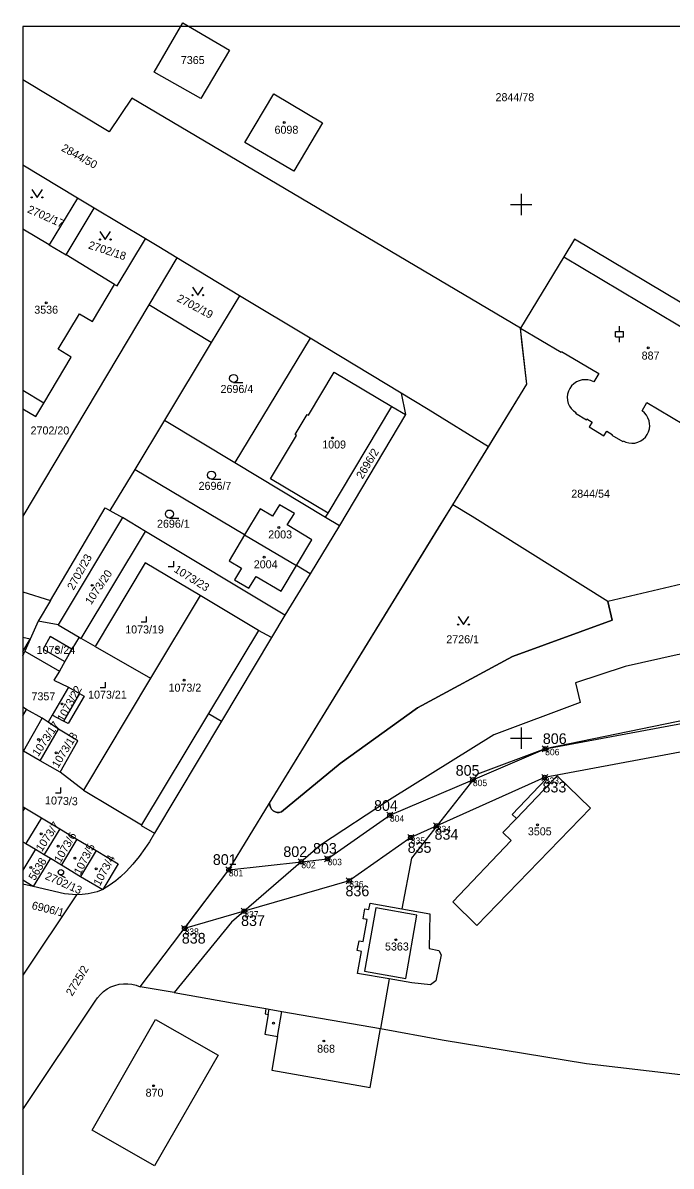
# Model space of a CAD drawing. Extents: x -800194 to -799078, y -1007177 to -1006597.
# Drawn here: x -800193.4 to -800071.9, y -1006980.2 to -1006766 of the extents above; entities that cross this region are included whole.
import ezdxf

# ---------------------------------------------------------------- set-up
doc = ezdxf.new("R2010")
doc.units = 0
for name, color, linetype in [('Dočasné zábory', 7, 'Continuous'), ('Legenda 1', 7, 'Continuous'), ('Ramove udaje', 7, 'Continuous'), ('Vrstva 53', 7, 'Continuous'), ('Vrstva 55', 7, 'Continuous'), ('Vrstva 56', 7, 'Continuous'), ('Vrstva 57', 7, 'Continuous'), ('Vrstva 58', 7, 'Continuous'), ('Vrstva 59', 7, 'Continuous'), ('Vrstva 60', 7, 'Continuous')]:
    doc.layers.add(name, color=color, linetype=linetype)

msp = doc.modelspace()

# ---------------------------------------------------------------- linework, layer by layer
at = {"layer": 'Dočasné zábory'}
for p, q in [((-800096.06, -1006902.6), (-800094.92, -1006901.46)), ((-800096.06, -1006901.46), (-800094.92, -1006902.6)), ((-800109.6, -1006908.39), (-800108.47, -1006907.25)), ((-800109.6, -1006907.25), (-800108.47, -1006908.39)), ((-800096.14, -1006907.95), (-800095.01, -1006906.82)), ((-800096.14, -1006906.82), (-800095.01, -1006907.95)), ((-800125.15, -1006915.04), (-800124.02, -1006913.9)), ((-800125.15, -1006913.9), (-800124.02, -1006915.04)), ((-800116.39, -1006917.03), (-800115.25, -1006915.9)), ((-800116.39, -1006915.9), (-800115.25, -1006917.03)), ((-800121.25, -1006919.21), (-800120.11, -1006918.08)), ((-800121.25, -1006918.08), (-800120.11, -1006919.21)), ((-800141.76, -1006923.76), (-800140.62, -1006922.63)), ((-800141.76, -1006922.63), (-800140.62, -1006923.76)), ((-800136.83, -1006923.21), (-800135.7, -1006922.08)), ((-800136.83, -1006922.08), (-800135.7, -1006923.21)), ((-800155.35, -1006925.3), (-800154.21, -1006924.16)), ((-800155.35, -1006924.16), (-800154.21, -1006925.3)), ((-800132.78, -1006927.34), (-800131.64, -1006926.21)), ((-800132.78, -1006926.21), (-800131.64, -1006927.34)), ((-800152.46, -1006933.02), (-800151.33, -1006931.88)), ((-800152.46, -1006931.88), (-800151.33, -1006933.02)), ((-800163.65, -1006936.24), (-800162.52, -1006935.11)), ((-800163.65, -1006935.11), (-800162.52, -1006936.24))]:
    msp.add_line(p, q, dxfattribs=at)
msp.add_lwpolyline([(-799934.68, -1006921.09), (-799969.58, -1006905.87), (-799994.89, -1006899.12), (-800033.61, -1006895.83), (-800040.39, -1006897.1), (-800095.58, -1006907.39), (-800115.82, -1006916.46), (-800120.68, -1006918.64), (-800132.21, -1006926.78), (-800151.89, -1006932.45), (-800163.09, -1006935.68), (-800154.78, -1006924.73), (-800141.19, -1006923.2), (-800136.27, -1006922.64), (-800124.59, -1006914.47), (-800109.03, -1006907.82), (-800095.49, -1006902.03), (-800049.12, -1006893.41), (-800047.13, -1006893.07), (-800033.82, -1006890.8), (-799994.03, -1006894.18), (-799967.93, -1006901.13), (-799932.44, -1006916.61)], dxfattribs=at)
for centre in [(-800095.49, -1006902.03), (-800109.03, -1006907.82), (-800095.58, -1006907.39), (-800124.59, -1006914.47), (-800115.82, -1006916.46), (-800120.68, -1006918.64), (-800141.19, -1006923.2), (-800136.27, -1006922.64), (-800154.78, -1006924.73), (-800132.21, -1006926.78), (-800151.89, -1006932.45), (-800163.09, -1006935.68)]:
    msp.add_circle(centre, 0.4, dxfattribs=at)
at = {"layer": 'Legenda 1'}
msp.add_lwpolyline([(-800193.4, -1007176.65), (-799312.4, -1007176.65), (-799312.4, -1006766.65), (-800193.4, -1006766.65)], close=True, dxfattribs=at)
at = {"layer": 'Ramove udaje'}
for p, q in [((-800100, -1006798), (-800100, -1006802)), ((-800102, -1006800), (-800100, -1006800)), ((-800100, -1006800), (-800098, -1006800)), ((-800100, -1006898), (-800100, -1006902)), ((-800102, -1006900), (-800100, -1006900)), ((-800100, -1006900), (-800098, -1006900))]:
    msp.add_line(p, q, dxfattribs=at)
at = {"layer": 'Vrstva 53'}
msp.add_lwpolyline([(-800067.83, -1006870.66), (-800083.75, -1006874.38), (-800082.93, -1006877.89), (-800101.58, -1006884.73), (-800119.41, -1006894.35), (-800133.89, -1006904.78), (-800144.92, -1006913.85), (-800145.32, -1006913.94), (-800145.72, -1006913.94), (-800146.12, -1006913.83), (-800146.47, -1006913.63), (-800146.77, -1006913.35), (-800147, -1006912.99), (-800147.12, -1006912.61), (-800147.15, -1006912.2), (-800112.81, -1006856.29), (-800098.93, -1006833.67), (-800100.11, -1006823.15), (-800172.96, -1006780.08), (-800177.22, -1006786.39), (-800193.4, -1006776.62)], dxfattribs=at)
at = {"layer": 'Vrstva 55'}
for p, q in [((-800183.18, -1006798.79), (-800193.4, -1006792.65)), ((-800180.01, -1006800.69), (-800183.18, -1006798.79)), ((-800170.41, -1006806.46), (-800180.01, -1006800.69)), ((-800164.51, -1006810.02), (-800169.77, -1006818.83)), ((-800152.8, -1006817.1), (-800164.51, -1006810.02)), ((-800152.8, -1006817.1), (-800158.09, -1006825.87)), ((-800139.57, -1006825.06), (-800152.8, -1006817.1)), ((-800158.09, -1006825.87), (-800169.77, -1006818.83)), ((-800158.09, -1006825.87), (-800166.86, -1006840.41)), ((-800139.57, -1006825.06), (-800153.65, -1006848.37)), ((-800122.47, -1006835.35), (-800139.57, -1006825.06)), ((-800122.47, -1006835.35), (-800121.67, -1006839.36)), ((-800166.86, -1006840.41), (-800172.41, -1006849.68)), ((-800166.86, -1006840.41), (-800153.65, -1006848.37)), ((-800121.67, -1006839.36), (-800134.05, -1006860.17)), ((-800112.81, -1006856.29), (-800106.13, -1006845.4)), ((-800172.41, -1006849.68), (-800177.12, -1006857.35)), ((-800153.65, -1006848.37), (-800136.64, -1006858.61)), ((-800177.12, -1006857.35), (-800174.74, -1006858.64)), ((-800136.64, -1006858.61), (-800134.05, -1006860.17)), ((-800174.74, -1006858.64), (-800186.75, -1006878.76)), ((-800170.43, -1006861.26), (-800174.74, -1006858.64)), ((-800134.05, -1006860.17), (-800139.55, -1006869.21)), ((-800182.47, -1006881.33), (-800170.43, -1006861.26)), ((-800144.27, -1006876.97), (-800170.43, -1006861.26)), ((-800151.83, -1006861.89), (-800142.1, -1006867.68)), ((-800139.55, -1006869.21), (-800144.27, -1006876.97)), ((-800139.55, -1006869.21), (-800142.1, -1006867.68)), ((-800067.83, -1006870.66), (-800083.75, -1006874.38)), ((-800193.4, -1006872.57), (-800188.22, -1006874.2)), ((-800160.18, -1006873.27), (-800169.49, -1006888.81)), ((-800188.22, -1006874.2), (-800190.53, -1006878.1)), ((-800144.27, -1006876.97), (-800146.81, -1006881.14)), ((-800190.53, -1006878.1), (-800192.02, -1006881.48)), ((-800186.75, -1006878.76), (-800190.53, -1006878.1)), ((-800186.75, -1006878.76), (-800182.83, -1006881.12)), ((-800192.02, -1006881.48), (-800193.4, -1006881.15)), ((-800192.02, -1006881.48), (-800193.01, -1006883.73)), ((-800182.83, -1006881.12), (-800182.47, -1006881.33)), ((-800179.85, -1006882.84), (-800182.47, -1006881.33)), ((-800193.4, -1006884.61), (-800193.01, -1006883.73)), ((-800193.01, -1006883.73), (-800186.55, -1006887.44)), ((-800179.85, -1006882.84), (-800169.49, -1006888.81)), ((-800186.55, -1006887.44), (-800187.59, -1006889.15)), ((-800184.82, -1006890.46), (-800187.9, -1006895.7)), ((-800187.59, -1006889.15), (-800184.82, -1006890.46)), ((-800169.49, -1006888.81), (-800182.05, -1006909.75)), ((-800192.7, -1006894.63), (-800193.4, -1006894.24)), ((-800193.4, -1006895.86), (-800192.7, -1006894.63)), ((-800189.78, -1006896.28), (-800192.7, -1006894.63)), ((-800193.28, -1006902.47), (-800189.78, -1006896.28)), ((-800188.68, -1006897.03), (-800189.78, -1006896.28)), ((-800187.9, -1006895.7), (-800188.68, -1006897.03)), ((-800186.7, -1006898.36), (-800188.68, -1006897.03)), ((-800190.15, -1006904.25), (-800186.7, -1006898.36)), ((-800183.1, -1006900.51), (-800186.7, -1006898.36)), ((-800186.38, -1006906.38), (-800183.1, -1006900.51)), ((-800193.28, -1006902.47), (-800193.4, -1006902.4)), ((-800190.15, -1006904.25), (-800193.28, -1006902.47)), ((-800186.38, -1006906.38), (-800190.15, -1006904.25)), ((-800182.05, -1006909.75), (-800186.38, -1006906.38)), ((-800193.05, -1006913.06), (-800193.4, -1006913.64)), ((-800193.05, -1006913.06), (-800189.92, -1006914.94)), ((-800189.92, -1006914.94), (-800192.83, -1006919.78)), ((-800189.92, -1006914.94), (-800186.48, -1006917.01)), ((-800186.48, -1006917.01), (-800189.39, -1006921.85)), ((-800186.48, -1006917.01), (-800183.26, -1006918.94)), ((-800193.4, -1006919.44), (-800192.83, -1006919.78)), ((-800192.83, -1006919.78), (-800191.06, -1006920.85)), ((-800183.26, -1006918.94), (-800186.17, -1006923.78)), ((-800183.26, -1006918.94), (-800179.67, -1006921.09)), ((-800191.06, -1006920.85), (-800193.4, -1006924.74)), ((-800188.23, -1006922.55), (-800191.44, -1006927.83)), ((-800191.06, -1006920.85), (-800189.39, -1006921.85)), ((-800189.39, -1006921.85), (-800188.23, -1006922.55)), ((-800188.23, -1006922.55), (-800186.17, -1006923.78)), ((-800179.67, -1006921.09), (-800182.6, -1006925.93)), ((-800120.56, -1006922.5), (-800122.37, -1006932)), ((-800186.17, -1006923.78), (-800182.6, -1006925.93)), ((-800191.44, -1006927.83), (-800193.4, -1006926.67)), ((-800182.6, -1006925.93), (-800178.43, -1006928.42)), ((-800191.44, -1006927.83), (-800193.4, -1006927.37)), ((-800183.37, -1006929.41), (-800193.4, -1006944.43)), ((-800124.76, -1006945.16), (-800126.38, -1006954.46)), ((-800165.04, -1006947.7), (-800171.39, -1006946.62))]:
    msp.add_line(p, q, dxfattribs=at)
for points in [[(-800163.38, -1006765.95), (-800154.63, -1006771.06), (-800160.01, -1006780.11), (-800168.77, -1006775.17), (-800163.38, -1006765.95)], [(-800100.11, -1006823.15), (-800172.96, -1006780.08), (-800177.22, -1006786.39), (-800193.4, -1006776.62)], [(-800146.37, -1006779.25), (-800137.24, -1006784.69), (-800142.62, -1006793.72), (-800151.76, -1006788.38), (-800146.37, -1006779.25)], [(-800183.18, -1006798.79), (-800188.44, -1006807.58), (-800193.4, -1006804.6)], [(-800176.19, -1006814.96), (-800185.31, -1006809.46), (-800180.01, -1006800.69)], [(-800176.19, -1006814.96), (-800175.72, -1006815.24), (-800170.41, -1006806.46)], [(-800164.51, -1006810.02), (-800167.92, -1006807.96), (-800170.41, -1006806.46)], [(-800020.66, -1006847.86), (-800026.06, -1006844.58), (-800089.97, -1006806.47), (-800092.01, -1006809.83), (-800100.11, -1006823.15)], [(-800193.4, -1006838.29), (-800190.96, -1006839.75), (-800189.46, -1006837.23), (-800184.32, -1006828.6), (-800186.75, -1006827.14), (-800182.78, -1006820.48), (-800180.34, -1006821.93), (-800176.19, -1006814.96)], [(-800169.77, -1006818.83), (-800193.4, -1006858.41)], [(-800106.13, -1006845.4), (-800098.93, -1006833.67), (-800099.83, -1006825.69), (-800100.11, -1006823.15)], [(-800100.11, -1006823.15), (-800092.48, -1006827.68), (-800092.4, -1006827.53), (-800085.43, -1006831.67), (-800086.36, -1006833.24)], [(-800086.36, -1006833.24), (-800086.9, -1006833.01), (-800087.46, -1006832.87), (-800088.05, -1006832.83), (-800088.53, -1006832.88), (-800089.09, -1006833.02), (-800089.63, -1006833.26), (-800090.11, -1006833.59), (-800090.53, -1006833.99), (-800090.88, -1006834.46), (-800091.13, -1006834.97), (-800091.29, -1006835.52), (-800091.35, -1006836.09), (-800091.31, -1006836.66), (-800091.3, -1006836.72), (-800091.15, -1006837.27), (-800090.91, -1006837.79), (-800090.58, -1006838.25), (-800090.17, -1006838.66), (-800089.7, -1006838.98)], [(-800106.13, -1006845.4), (-800117.43, -1006838.45), (-800120.08, -1006836.82), (-800122.47, -1006835.35)], [(-800077.33, -1006838.69), (-800076.4, -1006837.12), (-800069.48, -1006841.22), (-800069.56, -1006841.35), (-800061.89, -1006845.9), (-800061.61, -1006845.43), (-800053.39, -1006850.31), (-800053.68, -1006850.78), (-800042.78, -1006857.25)], [(-800136.64, -1006858.61), (-800136.18, -1006857.85), (-800124.24, -1006837.87), (-800121.67, -1006839.36)], [(-800089.7, -1006838.98), (-800089.78, -1006839.11), (-800087.76, -1006840.33), (-800087.69, -1006840.2), (-800086.68, -1006840.8), (-800087.24, -1006841.68), (-800084.46, -1006843.37), (-800083.93, -1006842.46), (-800082.91, -1006843.08), (-800082.98, -1006843.21), (-800080.94, -1006844.44), (-800080.86, -1006844.31)], [(-800080.86, -1006844.31), (-800080.34, -1006844.55), (-800079.78, -1006844.7), (-800079.21, -1006844.75), (-800078.65, -1006844.71), (-800078.09, -1006844.56), (-800077.57, -1006844.32), (-800077.09, -1006843.99), (-800076.68, -1006843.59), (-800076.35, -1006843.12), (-800076.1, -1006842.6), (-800075.95, -1006842.04), (-800075.89, -1006841.47), (-800075.91, -1006841.1), (-800076.01, -1006840.53), (-800076.22, -1006839.99), (-800076.51, -1006839.49), (-800076.89, -1006839.06), (-800077.33, -1006838.69)], [(-800151.83, -1006861.89), (-800172.32, -1006849.75), (-800172.41, -1006849.68)], [(-800142.1, -1006867.68), (-800139.22, -1006862.87), (-800143.86, -1006860.02), (-800142.5, -1006857.92), (-800145.28, -1006856.27), (-800146.57, -1006858.42), (-800148.9, -1006857.02), (-800151.83, -1006861.89)], [(-800147.15, -1006912.2), (-800114.97, -1006859.8), (-800112.81, -1006856.29)], [(-800083.75, -1006874.38), (-800109.15, -1006858.49), (-800112.81, -1006856.29)], [(-800188.22, -1006874.2), (-800177.98, -1006856.88), (-800177.12, -1006857.35)], [(-800151.83, -1006861.89), (-800154.75, -1006866.76), (-800152.43, -1006868.16), (-800153.72, -1006870.34), (-800151.03, -1006871.91), (-800149.68, -1006869.74), (-800144.98, -1006872.49), (-800142.1, -1006867.68)], [(-800160.18, -1006873.27), (-800170.48, -1006867.17), (-800179.85, -1006882.84)], [(-800146.81, -1006881.14), (-800149.24, -1006879.83), (-800160.18, -1006873.27)], [(-800144.92, -1006913.85), (-800133.89, -1006904.78), (-800119.41, -1006894.35), (-800101.58, -1006884.73), (-800082.93, -1006877.89), (-800083.75, -1006874.38)], [(-799964.79, -1006890.84), (-799979.01, -1006885.96), (-799998.45, -1006881.67), (-800018.08, -1006879.48), (-800038.51, -1006879.76), (-800056.43, -1006881.95), (-800070.76, -1006884.38), (-800080.47, -1006886.59), (-800089.79, -1006889.63), (-800088.91, -1006893.34), (-800105.12, -1006899.41), (-800124.67, -1006911.59), (-800137.62, -1006920.11), (-800154.3, -1006934.53), (-800165.04, -1006947.7)], [(-800193.4, -1006883.76), (-800192.02, -1006881.48)], [(-800182.83, -1006881.12), (-800184.21, -1006883.32), (-800185.51, -1006885.63), (-800186.55, -1006887.44)], [(-800146.81, -1006881.14), (-800156.19, -1006896.85), (-800168.72, -1006917.84)], [(-800184.82, -1006890.46), (-800182.76, -1006891.66), (-800181.9, -1006892.16), (-800184.93, -1006897.3), (-800185.8, -1006896.83), (-800187.9, -1006895.7)], [(-800048.34, -1006892.35), (-800095.49, -1006902.03), (-800108.2, -1006906.76), (-800120.56, -1006922.5)], [(-800094.49, -1006908.41), (-800093.24, -1006907.11), (-800087, -1006913.15), (-800108.28, -1006935.11), (-800112.78, -1006930.68), (-800101.83, -1006919.22), (-800103.39, -1006917.73), (-800100.86, -1006915.08), (-800101.66, -1006914.32), (-800095.28, -1006907.65), (-800094.49, -1006908.41)], [(-800182.05, -1006909.75), (-800171.15, -1006916.28), (-800171.22, -1006916.39), (-800168.72, -1006917.84)], [(-800171.39, -1006946.62), (-800154.78, -1006924.73), (-800147.15, -1006912.2)], [(-800147.15, -1006912.2), (-800147.12, -1006912.61), (-800147, -1006912.99), (-800146.78, -1006913.34), (-800146.77, -1006913.35), (-800146.47, -1006913.63), (-800146.12, -1006913.83), (-800145.72, -1006913.94), (-800145.32, -1006913.94), (-800144.92, -1006913.85)], [(-800193.4, -1006912.85), (-800193.05, -1006913.06)], [(-800168.72, -1006917.84), (-800169.66, -1006919.43), (-800170.52, -1006920.73), (-800171.62, -1006922.22), (-800172.79, -1006923.65), (-800174.04, -1006925.01), (-800175.11, -1006926.02), (-800176, -1006926.76), (-800177.19, -1006927.63), (-800178.43, -1006928.42)], [(-800179.67, -1006921.09), (-800175.54, -1006923.58), (-800178.43, -1006928.42)], [(-800183.37, -1006929.41), (-800185.59, -1006929.21), (-800191.44, -1006927.83)], [(-800178.43, -1006928.42), (-800179.48, -1006928.81), (-800180.04, -1006928.97), (-800181.14, -1006929.22), (-800182.25, -1006929.36), (-800183.37, -1006929.41)], [(-800124.76, -1006945.16), (-800130.67, -1006944.14), (-800129.93, -1006939.99), (-800130.7, -1006939.85), (-800130.36, -1006937.99), (-800129.59, -1006938.12), (-800128.86, -1006934.02), (-800129.62, -1006933.9), (-800129.29, -1006932.03), (-800128.52, -1006932.16), (-800128.31, -1006930.95), (-800122.37, -1006932)], [(-800122.37, -1006932), (-800117.1, -1006932.94), (-800117.23, -1006939.43), (-800115.39, -1006939.82), (-800114.95, -1006940.64), (-800115.98, -1006945.49), (-800117, -1006946.26), (-800120.48, -1006945.9), (-800124.76, -1006945.16)], [(-800179.84, -1006949.35), (-800179.39, -1006948.67), (-800178.86, -1006948.05), (-800178.26, -1006947.5), (-800177.6, -1006947.03), (-800176.89, -1006946.65), (-800176.16, -1006946.36), (-800175.37, -1006946.16), (-800174.56, -1006946.05), (-800173.75, -1006946.05), (-800172.94, -1006946.14), (-800172.15, -1006946.33), (-800171.39, -1006946.62)], [(-800165.04, -1006947.7), (-800154.15, -1006949.62), (-800147.83, -1006950.72)], [(-800193.4, -1006969.65), (-800179.84, -1006949.35)], [(-800147.83, -1006950.72), (-800148, -1006951.71), (-800147.41, -1006951.81), (-800148.05, -1006955.52), (-800145.68, -1006955.92), (-800146.75, -1006962.28), (-800128.29, -1006965.5), (-800126.38, -1006954.46)], [(-800147.83, -1006950.72), (-800147.24, -1006950.83), (-800144.85, -1006951.24), (-800126.38, -1006954.46)], [(-800156.78, -1006959.44), (-800168.69, -1006980.17), (-800180.42, -1006973.53), (-800168.51, -1006952.75), (-800156.78, -1006959.44)], [(-800126.38, -1006954.46), (-800114.82, -1006956.57), (-800087.75, -1006960.99), (-799990.59, -1006972.38), (-799910.85, -1006981.15)]]:
    msp.add_lwpolyline(points, dxfattribs=at)
at = {"layer": 'Vrstva 56'}
for p, q in [((-800188.44, -1006807.58), (-800185.31, -1006809.46)), ((-800092.01, -1006809.83), (-800054.01, -1006832.46)), ((-800139.86, -1006839.49), (-800135.03, -1006831.4)), ((-800135.03, -1006831.4), (-800124.24, -1006837.87)), ((-800189.46, -1006837.23), (-800193.4, -1006834.87)), ((-800142.38, -1006843.12), (-800140.12, -1006839.33)), ((-800140.12, -1006839.33), (-800139.86, -1006839.49)), ((-800146.98, -1006851.4), (-800142.12, -1006843.27)), ((-800142.12, -1006843.27), (-800142.38, -1006843.12)), ((-800136.18, -1006857.85), (-800146.98, -1006851.4)), ((-800149.24, -1006879.83), (-800158.6, -1006895.39)), ((-800188.29, -1006880.97), (-800189.61, -1006883.33)), ((-800184.21, -1006883.32), (-800188.29, -1006880.97)), ((-800189.61, -1006883.33), (-800185.51, -1006885.63)), ((-800182.76, -1006891.66), (-800185.8, -1006896.83)), ((-800158.6, -1006895.39), (-800171.15, -1006916.28)), ((-800158.6, -1006895.39), (-800156.19, -1006896.85)), ((-800100.86, -1006915.08), (-800094.49, -1006908.41)), ((-800127.23, -1006931.83), (-800129.33, -1006943.68)), ((-800119.52, -1006933.21), (-800127.23, -1006931.83)), ((-800121.59, -1006945.08), (-800119.52, -1006933.21)), ((-800129.33, -1006943.68), (-800121.59, -1006945.08)), ((-800147.41, -1006951.81), (-800147.24, -1006950.83)), ((-800145.68, -1006955.92), (-800144.85, -1006951.24))]:
    msp.add_line(p, q, dxfattribs=at)
at = {"layer": 'Vrstva 58'}
for p, q in [((-800082.29, -1006823.83), (-800080.79, -1006823.83)), ((-800082.29, -1006824.83), (-800082.29, -1006823.83)), ((-800081.54, -1006823.83), (-800081.54, -1006822.83)), ((-800080.79, -1006824.83), (-800080.79, -1006823.83)), ((-800082.29, -1006824.83), (-800080.79, -1006824.83)), ((-800081.54, -1006825.83), (-800081.54, -1006824.83)), ((-800153.9, -1006833.35), (-800152.15, -1006833.35)), ((-800158.04, -1006851.47), (-800156.29, -1006851.47)), ((-800165.92, -1006858.76), (-800164.17, -1006858.76)), ((-800165.12, -1006867.84), (-800165.12, -1006866.84)), ((-800166.13, -1006867.84), (-800165.12, -1006867.84)), ((-800170.24, -1006878.2), (-800170.24, -1006877.2)), ((-800171.24, -1006878.2), (-800170.24, -1006878.2)), ((-800178.93, -1006890.56), (-800177.92, -1006890.56)), ((-800177.92, -1006890.56), (-800177.92, -1006889.56)), ((-800186.28, -1006910.27), (-800186.28, -1006909.27)), ((-800187.28, -1006910.27), (-800186.28, -1006910.27)), ((-800186.51, -1006925.6), (-800185.47, -1006926.15))]:
    msp.add_line(p, q, dxfattribs=at)
for points in [[(-800191.74, -1006797.17), (-800190.74, -1006798.67), (-800189.74, -1006797.17)], [(-800178.94, -1006805.05), (-800177.94, -1006806.55), (-800176.94, -1006805.05)], [(-800161.61, -1006815.49), (-800160.61, -1006816.99), (-800159.61, -1006815.49)], [(-800111.8, -1006877.25), (-800110.8, -1006878.75), (-800109.8, -1006877.25)]]:
    msp.add_lwpolyline(points, dxfattribs=at)
for centre, radius in [((-800191.74, -1006798.67), 0.1), ((-800189.74, -1006798.67), 0.1), ((-800178.94, -1006806.55), 0.1), ((-800176.94, -1006806.55), 0.1), ((-800161.61, -1006816.99), 0.1), ((-800159.61, -1006816.99), 0.1), ((-800153.9, -1006832.6), 0.75), ((-800158.04, -1006850.72), 0.75), ((-800165.92, -1006858.01), 0.75), ((-800111.8, -1006878.75), 0.1), ((-800109.8, -1006878.75), 0.1), ((-800186.27, -1006925.16), 0.502)]:
    msp.add_circle(centre, radius, dxfattribs=at)
at = {"layer": 'Vrstva 59'}
for centre in [(-800144.39, -1006784.64), (-800189.01, -1006818.41), (-800076.15, -1006826.87), (-800135.34, -1006843.76), (-800145.42, -1006860.54), (-800148.15, -1006866.1), (-800180.42, -1006871.38), (-800187.09, -1006883.31), (-800163.18, -1006889.16), (-800186.06, -1006893.62), (-800190.48, -1006900.28), (-800187.14, -1006902.79), (-800096.93, -1006916.27), (-800189.96, -1006917.94), (-800186.79, -1006920.28), (-800183.63, -1006922.51), (-800191.89, -1006924.28), (-800179.65, -1006924.5), (-800123.47, -1006937.8), (-800146.41, -1006953.43), (-800136.95, -1006956.79), (-800168.88, -1006965.17)]:
    msp.add_circle(centre, 0.175, dxfattribs=at)
at = {"layer": 'Vrstva 60'}
for p, q in [((-800095.49, -1006902.03), (-800095.49, -1006902.03)), ((-800109.03, -1006907.82), (-800109.03, -1006907.82)), ((-800095.58, -1006907.39), (-800095.58, -1006907.39)), ((-800124.59, -1006914.47), (-800124.59, -1006914.47)), ((-800115.82, -1006916.46), (-800115.82, -1006916.46)), ((-800120.68, -1006918.64), (-800120.68, -1006918.64)), ((-800136.27, -1006922.64), (-800136.27, -1006922.64)), ((-800154.78, -1006924.73), (-800154.78, -1006924.73)), ((-800141.19, -1006923.2), (-800141.19, -1006923.2)), ((-800132.21, -1006926.78), (-800132.21, -1006926.78)), ((-800151.89, -1006932.45), (-800151.89, -1006932.45)), ((-800163.09, -1006935.68), (-800163.09, -1006935.68))]:
    msp.add_line(p, q, dxfattribs=at)

# ---------------------------------------------------------------- texts
at = {"layer": 'Dočasné zábory'}
for s, p in [('806', (-800095.92, -1006901.12)), ('805', (-800112.26, -1006907.07)), ('833', (-800095.98, -1006910.2)), ('804', (-800127.57, -1006913.65)), ('834', (-800116.22, -1006919.06)), ('802', (-800144.57, -1006922.3)), ('803', (-800139.01, -1006921.68)), ('835', (-800121.26, -1006921.52)), ('801', (-800157.78, -1006923.78)), ('836', (-800132.92, -1006929.66)), ('837', (-800152.49, -1006935.23)), ('838', (-800163.6, -1006938.53))]:
    msp.add_text(s, height=2, rotation=360, dxfattribs=at).set_placement(p)
at = {"layer": 'Vrstva 57'}
for s, p in [('7365', (-800163.78, -1006773.67)), ('2844/78', (-800104.79, -1006780.63)), ('6098', (-800146.22, -1006786.73)), ('3536', (-800191.26, -1006820.46)), ('887', (-800077.4, -1006829.06)), ('2696/4', (-800156.34, -1006835.32)), ('2702/20', (-800191.95, -1006843.1)), ('1009', (-800137.28, -1006845.73)), ('2696/7', (-800160.45, -1006853.48)), ('2844/54', (-800090.59, -1006854.95)), ('2696/1', (-800168.25, -1006860.58)), ('2003', (-800147.4, -1006862.59)), ('2004', (-800150.11, -1006868.19)), ('1073/19', (-800174.21, -1006880.4)), ('2726/1', (-800114.02, -1006882.24)), ('1073/24', (-800190.82, -1006884.22)), ('1073/2', (-800166.09, -1006891.31)), ('7357', (-800191.78, -1006892.93)), ('1073/21', (-800181.17, -1006892.62)), ('3505', (-800098.73, -1006918.24)), ('5363', (-800125.51, -1006939.83)), ('868', (-800138.23, -1006958.98)), ('870', (-800170.39, -1006967.23))]:
    msp.add_text(s, height=1.5, dxfattribs=at).set_placement(p)
for s, rotation, p in [('2844/50', 331, (-800186.32, -1006789.84)), ('2702/17', 336, (-800192.68, -1006801.44)), ('2702/18', 342, (-800181.24, -1006808.22)), ('2702/19', 332, (-800164.66, -1006818.05)), ('2696/2', 59, (-800129.73, -1006851.57)), ('2702/23', 61, (-800183.89, -1006872.4)), ('1073/20', 56, (-800180.61, -1006875.14)), ('1073/23', 328, (-800165.2, -1006868.76)), ('1073/22', 61, (-800185.78, -1006897.06)), ('1073/17', 56, (-800190.51, -1006903.56)), ('1073/18', 59, (-800186.78, -1006905.74)), ('1073/3', 358, (-800189.26, -1006912.41)), ('1073/7', 56, (-800189.86, -1006921.42)), ('1073/6', 60, (-800186.35, -1006923.53)), ('1073/5', 63, (-800182.61, -1006925.75)), ('5638', 59, (-800191.17, -1006926.84)), ('1073/4', 62, (-800178.95, -1006927.85)), ('2702/13', 336, (-800189.37, -1006926.38)), ('6906/1', 346, (-800191.84, -1006932.03)), ('2725/2', 59, (-800184.15, -1006948.49))]:
    msp.add_text(s, height=1.5, rotation=rotation, dxfattribs=at).set_placement(p)
at = {"layer": 'Vrstva 60'}
for s, p in [('806', (-800095.49, -1006903.23)), ('805', (-800109.03, -1006909.02)), ('833', (-800095.58, -1006908.59)), ('804', (-800124.59, -1006915.67)), ('834', (-800115.82, -1006917.66)), ('835', (-800120.68, -1006919.84)), ('803', (-800136.27, -1006923.84)), ('801', (-800154.78, -1006925.93)), ('802', (-800141.19, -1006924.4)), ('836', (-800132.21, -1006927.98)), ('837', (-800151.89, -1006933.65)), ('838', (-800163.09, -1006936.88))]:
    msp.add_text(s, height=1.2, dxfattribs=at).set_placement(p)

doc.saveas('drawing.dxf')
